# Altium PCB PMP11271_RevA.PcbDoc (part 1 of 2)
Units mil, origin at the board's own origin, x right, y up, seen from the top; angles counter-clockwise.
Board outline 3600 x 2200 mil, 4 copper layers (Top Layer, Signal Layer 1, Signal Layer 2, Bottom Layer), stack 61.2 mil thick; 97 components, 68 nets, 279 pads, 71 vias.
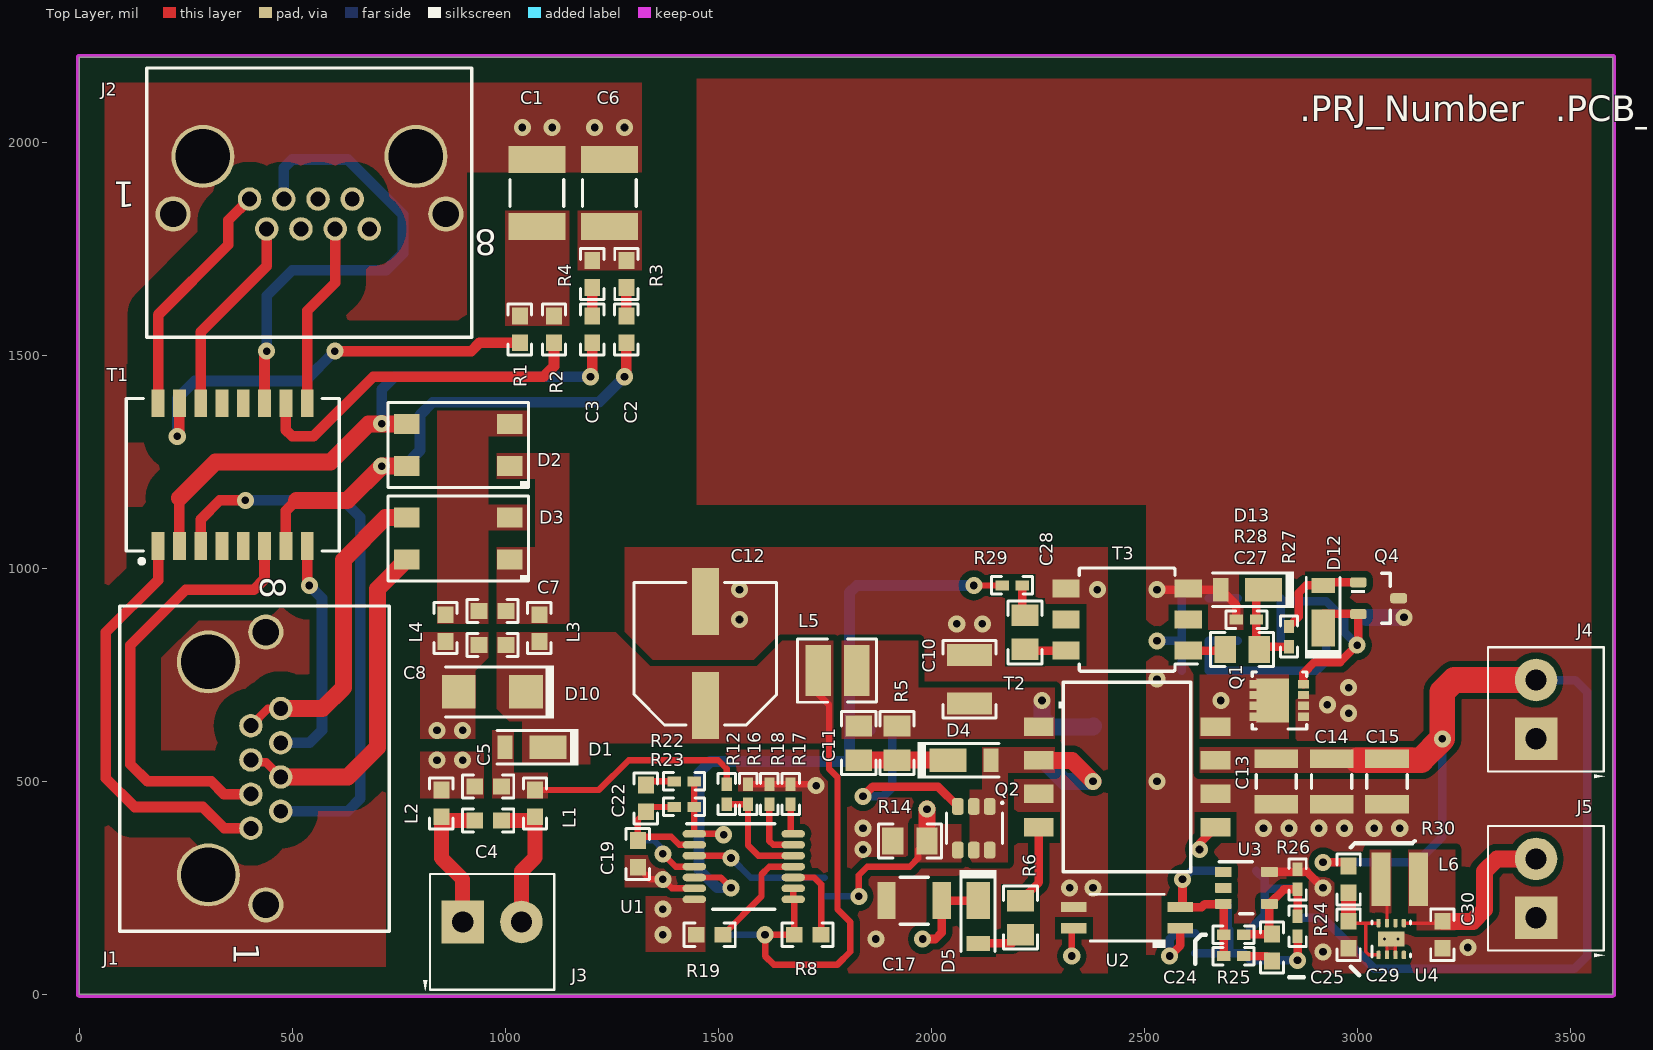
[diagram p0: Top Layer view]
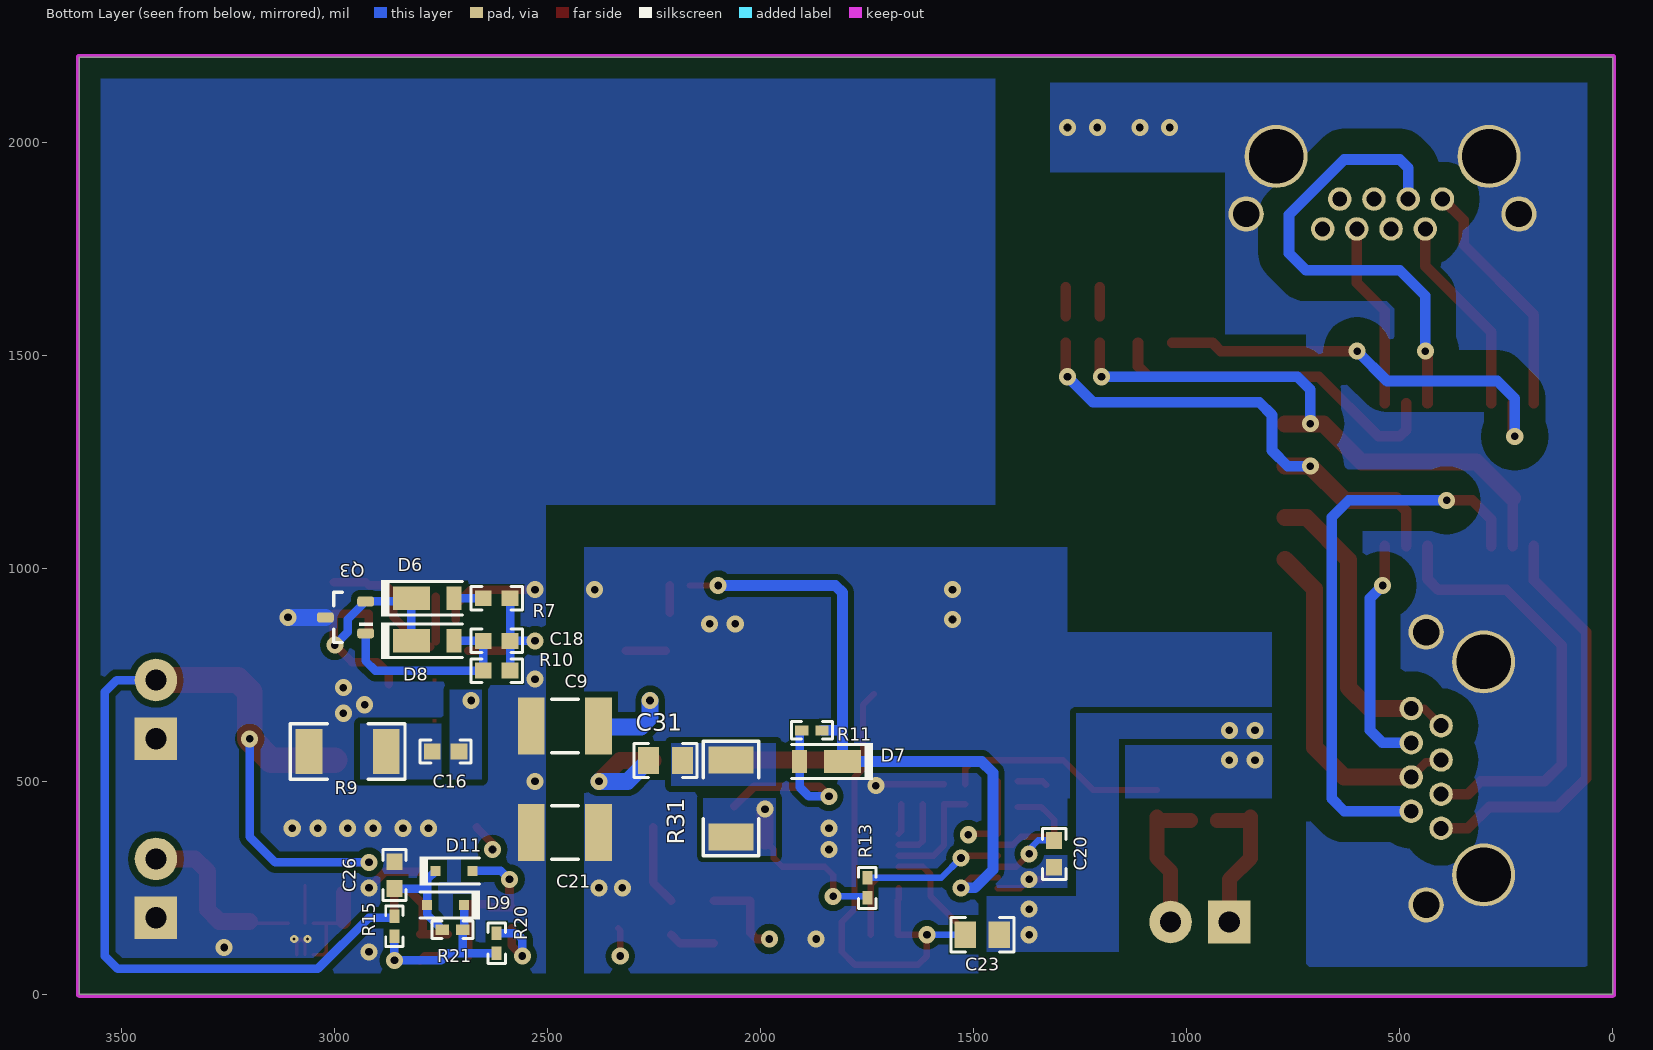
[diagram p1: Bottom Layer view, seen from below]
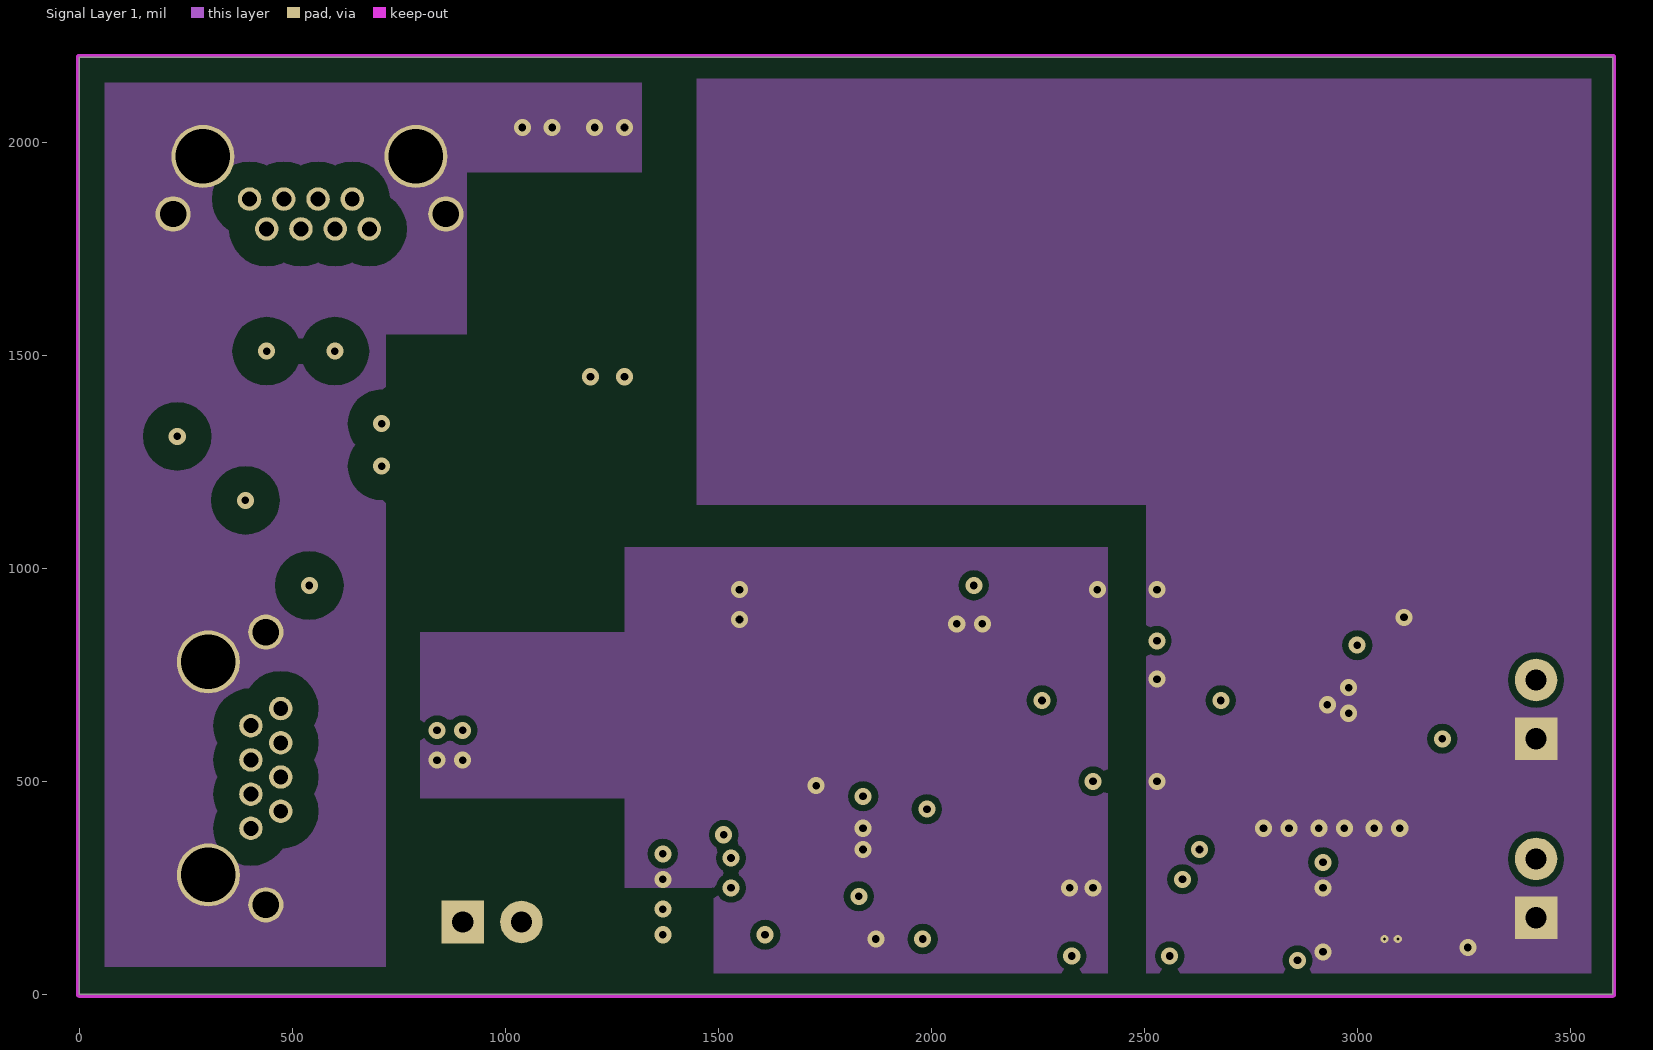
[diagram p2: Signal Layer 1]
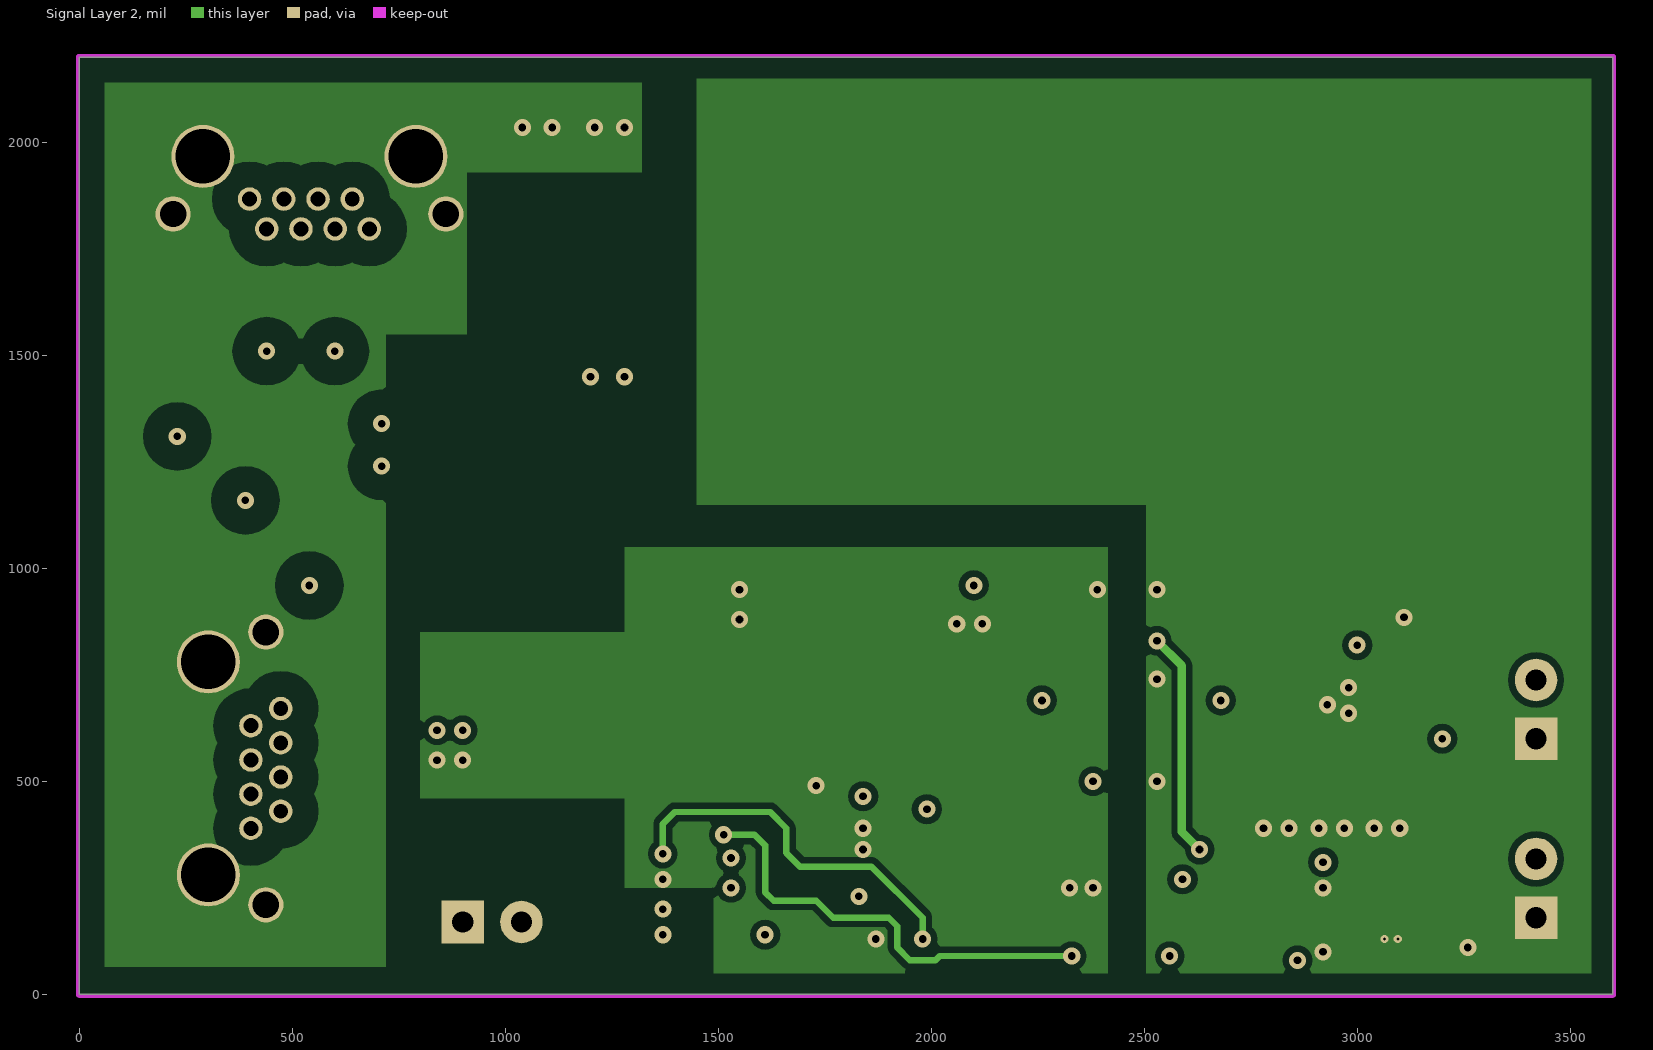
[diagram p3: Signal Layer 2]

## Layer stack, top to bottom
Top Solder: solder mask 0.4, Solder Resist, Dk 3.5
Top Layer: signal copper 2.8
Dielectric1: core 15, FR-4, Dk 4.8
Signal Layer 1: signal copper 2.8
Dielectric 3: prepreg 20, Dk 4.2
Signal Layer 2: signal copper 2.8
Dielectric 2: core 15, Dk 4.2
Bottom Layer: signal copper 2.8
Bottom Solder: solder mask 0.4, Solder Resist, Dk 3.5

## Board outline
0,0 3600,0 3600,2200 0,2200

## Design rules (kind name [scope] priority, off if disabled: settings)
AcuteAngle [All] p1: minimum=4.50000000000000E+0001 checktracksonly=FALSE
AssemblyTestPointUsage [All] p1: valid=2
Clearance Clearance_4 [InNamedPolygon('Signal Layer 2-EARTH')] p1: gap=60
Clearance Clearance_3 [InNamedPolygon('Signal Layer 1-EARTH')] p2: gap=60
Clearance Clearance_2 [InNamedPolygon('Top Layer-EARTH')] p3: gap=60
Clearance Clearance_1 [InNamedPolygon('Bottom Layer-EARTH')] p4: gap=60
Clearance Clearance_Keepouts [((IsTrack Or IsArc) And Not InPoly) And IsFree and IsKeepOut vs ((IsTrack Or IsArc) And Not InPoly) And IsFree and IsKeepOut] p5: gap=0
Clearance Clearance_BoardEdge_MountingHoles [OnCopper and InComponentClass('Mounting Holes') vs IsKeepOut] p6: gap=40
Clearance Clearance_BoardEdge_Poly [OnCopper and InPoly vs IsKeepOut] p7: gap=25
Clearance Clearance_BoardEdge [OnCopper and Not InComponentClass('Logo') and not InComponentClass('FiducialMark') and not InRegion(1000,500,4000,800) and Not IsKeepout vs IsKeepOut] p8: gap=50
Clearance Clearance_Poly [InPolygon] p9: gap=15
Clearance [All] p10: gap=7.87
ComponentClearance ComponentClearance_MountingHoles_FiducialMarks [InComponentClass('Mounting Holes') vs InComponentClass('FiducialMark')] p1: gap=50 collisioncheckmode=3 verticalgap=10 showdistances=FALSE
ComponentClearance ComponentClearance_Shunt [InComponentClass('Header') vs InComponentClass('Shunt')] p2: gap=0 collisioncheckmode=3 verticalgap=0 showdistances=FALSE
ComponentClearance ComponentClearance_Logo [InComponentClass('Logo')] p3: gap=50 collisioncheckmode=3 verticalgap=10 showdistances=FALSE
ComponentClearance ComponentClearance_ScrewToNut [(HasFootprint('NY PMS 440 0025 PH')) vs (HasFootprint('Keystone_1902C'))] p4: gap=5 collisioncheckmode=3 verticalgap=10 showdistances=FALSE
ComponentClearance ComponentClearance_MountingHoles [InComponentClass('Mounting Holes')] p5: gap=250 collisioncheckmode=3 verticalgap=100000 showdistances=FALSE
ComponentClearance ComponentClearance_SmallPassives [HasFootprint('0201*') or HasFootprint('0402*') or HasFootprint('0508') or HasFootprint('0603*') or HasFootprint('0612') or HasFootprint('0805*') or HasFootprint('0815*') or HasFootprint('0830*') or HasFootprint('1206*') or HasFootprint('1210*') or HasFootprint('1808*') or HasFootprint('1812*') or HasFootprint('1825*') or HasFootprint('2010*') or HasFootprint('2220*') or HasFootprint('2225*') or HasFootprint('2512*') or HasFootprint('2728*') or HasFootprint('3518*') vs HasFootprint('0201*') or HasFootprint('0402*') or HasFootprint('0508') or HasFootprint('0603*') or HasFootprint('0612') or HasFootprint('0805*') or HasFootprint('0815*') or HasFootprint('0830*') or HasFootprint('1206*') or HasFootprint('1210*') or HasFootprint('1808*') or HasFootprint('1812*') or HasFootprint('1825*') or HasFootprint('2010*') or HasFootprint('2220*') or HasFootprint('2225*') or HasFootprint('2512*') or HasFootprint('2728*') or HasFootprint('3518*')] p6: gap=20 collisioncheckmode=3 verticalgap=10 showdistances=FALSE
ComponentClearance ComponentClearance_THtoSMT [IsThruComponent vs IsSMTComponent] p7: gap=50 collisioncheckmode=3 verticalgap=30 showdistances=FALSE
ComponentClearance ComponentClearance_THtoTH [IsThruComponent vs IsThruComponent] p8: gap=50 collisioncheckmode=3 verticalgap=30 showdistances=FALSE
ComponentClearance [All] p9: gap=20 collisioncheckmode=3 verticalgap=10 showdistances=FALSE
DiffPairsRouting [All] p1: maxlimit=100 minlimit=10 mostfreqgap=10 toplayer_minwidth=15 toplayer_maxwidth=15 toplayer_prefwidth=15 midlayer1_minwidth=15 midlayer1_maxwidth=15 midlayer1_prefwidth=15 midlayer2_minwidth=15 midlayer2_maxwidth=15 midlayer2_prefwidth=15 bottomlayer_minwidth=15 bottomlayer_maxwidth=15 bottomlayer_prefwidth=15 maxuncoupledlength=1000
FabricationTestPointUsage TestPointUsage [All] p1: valid=2 allowmultiple=FALSE
FabricationTestpoint Testpoint [All] p1: side=3 testpointundercomponent=TRUE minsize=40 maxsize=100 preferedsize=60 minholesize=0 maxholesize=40 preferedholesize=32 testpointgrid=1 allowsidetop=TRUE allowsidebottom=TRUE usegrid=TRUE gridtolerance=0.01
FanoutControl Fanout_LCC [IsLCC] p1: bgadir=Out bgaviamode=Centered fanoutstyle=Auto fanoutdirection=Alternating viagrid=1 // Fanout_LCC (Default Rule)
FanoutControl Fanout_BGA [IsBGA] p2: bgadir=Out bgaviamode=Centered fanoutstyle=Auto fanoutdirection=Alternating viagrid=1 // Fanout_BGA (Default Rule)
FanoutControl Fanout_Default [All] p4: bgadir=Out bgaviamode=Centered fanoutstyle=Auto fanoutdirection=Alternating viagrid=1 // Fanout_Default (Default Rule)
FanoutControl Fanout_Small [(CompPinCount < 5)] p5: bgadir=Out bgaviamode=Centered fanoutstyle=Auto fanoutdirection=OutThenIn viagrid=1 // Fanout_Small (Default Rule)
HoleSize [All] p1: absolutevalues=TRUE maxlimit=251 minlimit=8 maxpercent=80.000 minpercent=20.000
MinimumAnnularRing MinimumAnnularRing_ThermalPadVias [IsVia and InAnyComponent] p1: minimumring=5.91
MinimumAnnularRing [All] p2: minimumring=9
MinimumSolderMaskSliver MinimumSolderMaskSliver_Logo [InComponentClass('Logo') vs InComponentClass('Logo')] p1: minsoldermaskwidth=0.7
MinimumSolderMaskSliver [All] p2: minsoldermaskwidth=3.94
PlaneConnect [All] p1: planeconnectstyle=Relief reliefexpansion=10 reliefentries=4 reliefconductorwidth=10 reliefairgap=10
PolygonConnect [All] p1: connectstyle=Direct reliefconductorwidth=10 reliefentries=4 polygonreliefangle="90 Angle" airgapwidth=10
RoutingVias ThermalPadVias [IsVia and InAnyComponent] p1: holewidth=7.87 width=19.68 viastyle="Through Hole" minholewidth=7.87 minwidth=19.68 maxholewidth=12.99 maxwidth=23.62
RoutingVias [All] p2: holewidth=18 width=40 viastyle="Through Hole" minholewidth=7.87 minwidth=26 maxholewidth=40 maxwidth=65
SilkToBoardRegionClearance [Not ((IsComment or IsDesignator) And (Hide <> 'False')) and not InRegion(1000,500,4000,800)] p1:
SilkToSilkClearance SilkToSilkClearance_Pb-FreeLogo [(HasFootprint('Pb-Free_Overlay_Medium') OR HasFootprint('Pb-Free_Overlay_Small')) vs (HasFootprint('Pb-Free_Overlay_Medium') OR HasFootprint('Pb-Free_Overlay_Small'))] p1: silktosilkclearance=0
SilkToSilkClearance [All] p2: silktosilkclearance=2
SilkToSolderMaskClearance "Silk to Solder Mask Opening" [All] p1: minsilkscreentomaskgap=2 clearancetoexposedcopper=FALSE
SolderMaskExpansion [All] p1: expansion=1.97
UnpouredPolygon [All] p1: allowunpoured=FALSE
Width [All] p1: maxlimit=100 minlimit=6 preferedwidth=10 checkconnectedcopper=TRUE
14 further rules are at their usual default settings.

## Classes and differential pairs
component class PMP11271_RevB_SH1: C1 C2 C3 C4 C5 C6 C7 C8 D1 D2 D3 J1 J2 J3 L1 L2 L3 L4 R1 R2 R3 R4 T1
component class PMP11271_RevB_SH2: C9 C10 C11 C12 C13 C14 C15 C16 C17 C18 C19 C20 C21 C22 C23 C24 C25 C26 C27 C28 C29 C30 C31 D4 D5 D6 D7 D8 D9 D10 D11 D12 D13 J4 J5 L5 L6 Q1 Q2 Q3 Q4 R5 R6 R7 R8 R9 R10 R11 R12 R13 R14 R15 R16 R17 R18 R19 R20 R21 R22 R23 R24 R25 R26 R27 R28 R29 R30 R31 T2 T3 U1 U2 U3 U4

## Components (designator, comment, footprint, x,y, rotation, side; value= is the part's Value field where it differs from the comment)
C1 "1812GC102KA1" 1812 1074.32,1881.17 r90 top
C2 "C1608X7R2A103K" 0603 1284.32,1561.17 r90 top
C3 "C1608X7R2A103K" 0603 1204.32,1561.17 r90 top
C4 "C1608X7R2A102K" 0603 960,408.35 r180 top
C5 "C1608X7R2A102K" 0603 960,488.35 r180 top
C6 "1812GC102KA1" 1812 1244.32,1881.17 r90 top
C7 "C1608X7R2A102K" 0603 970,900 r180 top
C8 "C1608X7R2A102K" 0603 970,820 r180 top
C9 "C4532X7R3D222K" 1812 2460,630 r180 bottom
C10 "GRM32ER72A225KA35L" 1210 2090,740 r90 top
C11 "C2012X7R2A104K" 0805_HV 1830,590 r270 top
C12 "EEE-FK1K100P" SM_RADIAL_E 1470,800 r90 top
C13 "C3225X5R0J107M" 1210L 2810,500 r270 top
C14 "C3225X5R0J107M" 1210L 2940,500 r270 top
C15 "C3225X5R0J107M" 1210L 3070,500 r270 top
C16 "GRM188R71H332KA01D" 0603 2740,570 r0 bottom
C17 "C3225X7R1C226K250AC" 1210_280 1960,220 r180 top
C18 "C1608C0G1H221J" 0603 2620,830 r180 bottom
C19 "C1608X7R1H104K" 0603 1311.32,330 r90 top
C20 "C1608X7R1C105K" 0603 1311.32,330 r270 bottom
C21 "C4532X7R3D222K" 1812 2460,380 r180 bottom
C22 "C1608X7R1H104K" 0603 1330,460 r90 top
C23 "C2012X7R2A104K" 0805_HV 1480,140 r180 bottom
C24 "GRM1535C1H101JDD5D" 0402 2710,140 r180 top
C25 "GRM188R71E123KA01D" 0603 2800,110 r270 top
C26 "C1608X7R1C105K" 0603 2860,280 r90 bottom
C27 "C2012X7R1E474K" 0805_HV 2730,810 r180 top
C28 "C2012X7R1E474K" 0805_HV 2220,850 r90 top
C29 "C1608X5R1A226M080AC" 0603_100 2980,140 r270 top
C30 "C1608X5R1A226M080AC" 0603_100 3200,140 r270 top
C31 "GRM21A5C2E680JW01D" 0805_HV 2223.78,549.37 r180 bottom
D1 "DFLS1100-7" powerDI123 1050,580 r180 top
D2 "HD01-T" MiniDIP 890,1290 r180 top
D3 "HD01-T" MiniDIP 890,1070 r180 top
D4 "DFLU1200-7" powerDI123 2090,550 r0 top
D5 "DFLU1200-7" powerDI123 2110,170 r270 top
D6 "DFLS1100-7" powerDI123 2770,930 r180 bottom
D7 "DFLU1200-7" powerDI123 1858.52,546.71 r0 bottom
D8 "DFLS1100-7" powerDI123 2770,830 r180 bottom
D9 "BAT54HT1G" sod-323 2740,210 r0 bottom
D10 "SMAJ58A" SMA 970,710 r180 top
D11 "BAT54HT1G" sod-323 2720,290 r180 bottom
D12 "DFLS1100-7" powerDI123 2920,910 r90 top
D13 "DFLS1100-7" powerDI123 2730,950 r180 top
J1 "1-406541-1" TEC_1-406541-1 410,530 r270 top
J2 "1-406541-1" TEC_1-406541-1 540,1860 r180 top
J3 "ED555/2DS" TERM_BLK_ED555-2DS 900,170 r0 top
J4 "ED555/2DS" TERM_BLK_ED555-2DS 3420,600 r90 top
J5 "ED555/2DS" TERM_BLK_ED555-2DS 3420,180 r90 top
L1 "MPZ1608S221A" 0603 1070,448.35 r90 top
L2 "MPZ1608S221A" 0603 850,448.35 r90 top
L3 "MPZ1608S221A" 0603 1080,860 r270 top
L4 "MPZ1608S221A" 0603 860,860 r270 top
L5 "ME3220-103KLB" ME3220 1780,760 r0 top
L6 "XFL3012-152MEB" XFL3012 3100,270 r0 top
Q1 "CSD17579Q3A" TRANS_NexFET_Q3A 2810,690 r180 top
Q2 "FDC86244" SOT-6 2100,390 r270 top
Q3 "MMBT3906" SOT-23 2975,885 r0 bottom
Q4 "MMBT3906" SOT-23 3050,930 r0 top
R1 "CRCW060375R0FKEA" 0603 1034.32,1561.17 r90 top
R2 "CRCW060375R0FKEA" 0603 1114.32,1561.17 r90 top
R3 "CRCW060375R0FKEA" 0603 1284.32,1691.17 r270 top
R4 "CRCW060375R0FKEA" 0603 1204.32,1691.17 r270 top
R5 "CRCW080539K0JNEA" 0805_HV 1920,590 r90 top
R6 "CRCW080520R0JNEA" 0805_HV 2210,180 r90 top
R7 "CRCW060310R0JNEA" 0603 2620,930 r0 bottom
R8 "CRCW060324K9FKEA" 0603 1710,140 r180 top
R9 "CRCW20102R20JNEF" 2010 2970,570 r180 bottom
R10 "CRCW06034K99FKEA" 0603 2620,760 r0 bottom
R11 "CRCW0402100RFKED" 0402 1880,620 r0 bottom
R12 "CRCW0402374KFKED" 0402 1520,470 r90 top
R13 "CRCW04021K00FKED" 0402 1750,250 r90 bottom
R14 "ERJ-6RQFR47V" 0805_HV 1950,360 r0 top
R15 "ERJ-2GE0R00X" 0402 2860,160 r90 bottom
R16 "CRCW040220K0FKED" 0402 1570,470 r270 top
R17 "CRCW040237K4FKED" 0402 1670,470 r270 top
R18 "CRCW0402100KFKED" 0402 1620,470 r270 top
R19 "CRCW060390R9FKEA" 0603 1480,140 r0 top
R20 "CRCW0402649RFKED" 0402 2620,120 r270 bottom
R21 "CRCW040210K0FKED" 0402 2723.76,151.79 r180 bottom
R22 "CRCW0402499RFKED" 0402 1420,500 r180 top
R23 "CRCW04022K00FKED" 0402 1420,440 r180 top
R24 "CRCW040210K0FKED" 0402 2860,160 r270 top
R25 "CRCW040210K0FKED" 0402 2710,90 r180 top
R26 "CRCW04023K24FKED" 0402 2860,270 r270 top
R27 "CRCW040210R0JNED" 0402 2840,840 r270 top
R28 "CRCW040210K0FKED" 0402 2740,880 r0 top
R29 "ERJ-2GE0R00X" 0402 2190,960 r180 top
R30 "ERJ-3GEY0R00V" 0603 2980,270 r270 top
R31 "CRCW201075R0JNEF" 2010 2070,460 r90 bottom
T1 "H2019FNLT" PULSE_H2019FNL 360,1220 r90 top
T2 "LDT0807-50" Linkcom_LDT0807-50 2460,510 r0 top
T3 "760301107" Wurth_WE-GDT_EP5 2460,880 r180 top
U1 "TPS23753APW" PW0014A_N 1560,300 r0 top
U2 "HMHA2801A" MFP04A 2460,180 r180 top
U3 "TLV431AIDBV" DBV0005A_N 2740,250 r0 top
U4 "TPS62082DSGR" DSG0008A 3080,130 r90 top

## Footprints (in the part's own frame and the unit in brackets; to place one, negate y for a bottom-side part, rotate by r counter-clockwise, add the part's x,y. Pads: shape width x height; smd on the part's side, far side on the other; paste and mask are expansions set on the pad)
0402 [mm] "0402 from SM-752 data"
  rect 0.8x0.6 smd: 1(-0.6,0) 2(0.6,0)
  silkscreen extent -1.22,-0.52 1.22,0.52, body extent -0.55,-0.3 0.55,0.3, height 0.6
0603 [mm] "0603 from SM-752 data"
  rect 1x0.95 smd: 1(-0.8,0) 2(0.8,0)
  silkscreen extent -1.52,-0.69 1.52,0.69, body extent -0.87,-0.47 0.87,0.47, height 0.85
0603_100 [mm] "SMD, 2-Leads, Body 1.6x0.8mm"
  rect 1x0.95 smd: 1(-0.8,0) 2(0.8,0)
  silkscreen extent -1.52,-0.69 1.52,0.69, body extent -0.87,-0.47 0.87,0.47, height 1
0805_HV [mil] "0805 with 30mil clearance between pads"
  rect 50x63 smd: 1(-40,0) 2(40,0)
  silkscreen extent -74,-40 74,40, body extent -43,-29 43,29, height 57
1210 [mm] "1210 from SM-752 data"
  rect 1.3x2.7 smd: 1(-1.45,0) 2(1.45,0)
  silkscreen extent -2.32,-1.57 2.32,1.57, body extent -1.7,-1.35 1.7,1.35, height 1.35
1210_280 [mm] "SMD, 2-Leads, Body 3.6x2.8mm, Height 2.8mm"
  rect 1.1x2.2 smd: 1(-1.65,0) 2(1.65,0)
  silkscreen extent -0.84,-1.4 0.84,1.4, body extent -1.8,-1.4 1.8,1.4, height 2.8
1210L [mm] "1210 from SM-752 data"
  rect 1.1x2.6 smd: 1(-1.35,0) 2(1.35,0)
  silkscreen extent -0.4,-1.2 0.4,1.2, body extent -1.7,-1.35 1.7,1.35, height 1.35
1812 [mm]
  rect 1.6x3.4 smd: 1(-2,0) 2(2,0)
  silkscreen extent -0.8,-1.6 0.8,1.6, body extent -2.4,-1.7 2.4,1.7, height 1.35
2010 [mm] "Chip Capacitor, Body 5.08x2.54mm, IPC Medium Density"
  rect 1.6x2.7 smd: 1(-2.3,0) 2(2.3,0)
  silkscreen extent -3.42,-1.65 3.42,1.65, body extent -2.73,-1.45 2.73,1.45, height 1.66
DBV0005A_N [mm] "SOT23, 5-Leads, Body 2.9x1.6mm, Pitch 0.95mm, Lead Span 2.8mm, IPC Medium Density"
  rrect17% 1x0.6 smd: 1(-1.375,0.95) 2(-1.375,0) 3(-1.375,-0.95) 4(1.375,-0.95) 5(1.375,0.95)
  silkscreen extent -1.63,-1.55 0.38,1.55, body extent -1.42,-1.46 1.42,1.46, height 1.09
DSG0008A [mm] "SON, 8-Leads, Body 2x2mm, Pitch 0.5mm, Thermal Pad 1.6x0.9mm, TI Recommended"
  rrect40% 0.5x0.25 smd: 1(-0.95,0.75) 2(-0.95,0.25) 3(-0.95,-0.25) 4(-0.95,-0.75) 5(0.95,-0.75) 6(0.95,-0.25) 7(0.95,0.25) 8(0.95,0.75)
  rrect11% 0.9x1.6 smd paste-0.45: 9(0,0)
  silkscreen extent -1.07,-1.15 1.07,1.15, body extent -1.05,-1.05 1.05,1.05, height 0.8
Linkcom_LDT0807-50 [mm] "SMD, 8-Leads, Body 11.3x7.6mm, Pitch 2mm"
  rect 1.77x1.1 smd: 1(-5.265,3) 2(-5.265,1) 3(-5.265,-1) 4(-5.265,-3) 5(5.265,-3) 6(5.265,-1) 7(5.265,1) 8(5.265,3)
  silkscreen extent -4.1,-5.65 3.8,5.65, body extent -6,-5.65 6,5.65, height 5.71
ME3220 [mm] "Coilcraft SMT Power Inductor ME3220 inductors"
  rect 1.52x3.05 smd: 1(-1.145,0) 2(1.145,0)
  silkscreen extent -2.38,-1.88 2.34,1.88, body extent -1.75,-1.41 1.75,1.4
MFP04A [mm] "FAIRCHILD optocoupler"
  rect 1.52x0.61 smd: 1(-3.175,0.635) 2(-3.175,-0.635) 3(3.175,-0.635) 4(3.175,0.635)
  silkscreen extent -2.28,-1.4 2.2,1.8, body extent -3.6,-1.34 3.6,1.34, height 2.39
MiniDIP [mm] "Land pattern created based on STEP model."
  rect 1.52x1.2 smd: 1(-3.075,1.25) 2(-3.075,-1.25) 3(3.075,-1.25) 4(3.075,1.25)
  silkscreen extent -4.19,-2.54 4.19,2.54, body extent -3.5,-2.45 3.5,2.45, height 2.75
powerDI123 [mm] "Diodes Inc recommended land pattern, document number DS30628 Rev. 6-2"
  rect 2.2x1.4 smd: 1(-1.275,0)
  rect 0.9x1.4 smd: 2(1.275,0)
  silkscreen extent -3.1,-1.09 1.76,1.09, body extent -2.38,-0.97 1.52,0.96, height 1
PULSE_H2019FNL [mil] "PULSE"
  rect 65x30 smd paste+0: 1(-167.51,174.99) 2(-167.51,124.99) 3(-167.51,74.99) 4(-167.51,24.99) 5(-167.51,-25.01) 6(-167.51,-75.01) 7(-167.51,-125.01) 8(-167.51,-175.01) 9(167.49,-175.01) 10(167.49,-125.01) 11(167.49,-75.01) 12(167.49,-25.01) 13(167.49,24.99) 14(167.49,74.99) 15(167.49,124.99) 16(167.49,174.99)
  silkscreen extent -208,-250 179,250, body extent -179,-250 179,250, height 236
PW0014A_N [mm] "TSOP, 14-Leads, Body 5x4.4mm, Pitch 0.65mm, IPC Medium Density"
  oval 1.4x0.45 smd: 1(-2.95,1.95) 2(-2.95,1.3) 3(-2.95,0.65) 4(-2.95,0) 5(-2.95,-0.65) 6(-2.95,-1.3) 7(-2.95,-1.95) 8(2.95,-1.95) 9(2.95,-1.3) 10(2.95,-0.65) 11(2.95,0) 12(2.95,0.65) 13(2.95,1.3) 14(2.95,1.95)
  silkscreen extent -3.4,-2.55 1.85,2.55, body extent -3.21,-2.5 3.21,2.5, height 1
SM_RADIAL_E [mm] "8 x 6.2mm:  Panasonic E"
  rect 4x1.6 smd: 1(-3.1,0) 2(3.1,0)
  silkscreen extent -4.25,-4.25 4.25,4.25, body extent -4.26,-4.26 4.26,4.26, height 6.5
SMA [mm] "Molded Diode, 2-Leads, Body 4.3x2.6mm, IPC Medium Density, based on OnSemi component dimensions and land pattern"
  rect 2x2 smd: 1(-2,0) 2(2,0)
  silkscreen extent -3.66,-1.57 2.79,1.57, body extent -2.6,-1.3 2.6,1.3, height 2.42
sod-323 [mm] "NXP recommended land pattern"
  rect 0.6x0.6 smd paste-0.05: 1(-1.1,0) 2(1.1,0)
  silkscreen extent -2.06,-0.86 1.53,0.86, body extent -1.3,-0.67 1.3,0.68, height 1.1
SOT-6 [mm] "Fairchild recommended land pattern for SuperSOT-6 in MA06A.pdf dated 17OCT2005"
  rrect50% 1x0.7 smd: 1(-1.3,0.95) 2(-1.3,0) 3(-1.3,-0.95) 4(1.3,-0.95) 5(1.3,0) 6(1.3,0.95)
  silkscreen extent -1.52,-1.64 0.9,1.71, body extent -1.43,-1.48 1.43,1.49, height 0.9
SOT-23 [mm] "SOT23, 3-Leads, Body 2.9x1.3mm, Pitch 0.95mm, Lead Span 2.5mm, IPC Medium Density"
  rrect50% 1x0.6 smd: 1(-1.2,0.95) 2(-1.2,-0.95) 3(1.2,0)
  silkscreen extent -1.62,-1.5 0.7,1.5, body extent -1.16,-1.45 1.21,1.45, height 1
TEC_1-406541-1 [mm] "TE Connectivity"
  round 1.4 hole 0.89: 1(3.56,-0.18) 2(2.54,1.6) 3(1.52,-0.18) 4(0.5,1.6) 5(-0.52,-0.18) 6(-1.54,1.6) 7(-2.56,-0.18) 8(-3.58,1.6)
  round 2.1 hole 1.57: 9(8.12,0.71) 10(-8.14,0.71)
  round 3.759 hole 3.251: 11(6.34,-2.72) 12(-6.36,-2.72)
  silkscreen extent -9.69,-8 9.69,8.06, body extent -9.33,-8 9.31,7.75, height 14.8
TERM_BLK_ED555-2DS [mil]
  rect 100x100 hole 50: 1(0,0)
  round 100 hole 50: 2(138,0)
  silkscreen extent -93,-161 215,113, body extent -69,-150 207,106, height 323
TRANS_NexFET_Q3A [mm] "TI"
  rect 0.68x0.5 smd paste-1 mask+0.076: 1(-1.625,0.975) 2(-1.625,0.325) 3(-1.625,-0.325) 4(-1.625,-0.975)
  rect 0.41x0.5 smd paste-1 mask+0.076: 5(1.385,-0.975) 6(1.385,-0.325) 7(1.385,0.325) 8(1.385,0.975)
  rect 1.96x2.65 smd paste-3 mask+0.076: 9(0.205,0)
  Top Layer region: 1,1.1 1.24,1.1 1.24,1.325 1,1.325
  Top Layer region: 1,-1.325 1.24,-1.325 1.24,-1.1 1,-1.1
  silkscreen extent -1.82,-1.7 1.42,1.7, body extent -1.85,-1.65 1.45,1.66, height 0.91
Wurth_WE-GDT_EP5 [mm] "Gate Drive Transformer, EP5"
  rect 1.63x1.07 smd: 1(-3.645,1.85) 2(-3.645,0) 3(-3.645,-1.85) 4(3.645,-1.85) 5(3.645,0) 6(3.645,1.85)
  silkscreen extent -4.2,-3.08 2.85,3.08, body extent -3.85,-3.08 3.85,3.07, height 5.12
XFL3012 [mm] "Coilcraft"
  rect 1.12x3.2 smd: 1(-1.11,0) 2(1.11,0)
  body extent -1.6,-1.6 1.6,1.6, height 1.3

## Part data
C1 C6: "CAP, CERM, 1000pF, 2000V, +/-10%, X7R, 1812"
C2 C3: "CAP, CERM, 0.01uF, 100V, +/-10%, X7R, 0603"
C4 C5 C7 C8: "CAP, CERM, 1000pF, 100V, +/-10%, X7R, 0603"
C9 C21: "CAP, CERM, 2200pF, 2000V, +/-10%, X7R, 1812"
C10: "CAP, CERM, 2.2uF, 100V, +/-10%, X7R, 1210"
C11 C23: "CAP, CERM, 0.1uF, 100V, +/-10%, X7R, 0805"
C12: "CAP, AL, 10 µF, 80 V, +/- 20%, 2.4 ohm, SMD"
C13 C14 C15: "CAP, CERM, 100uF, 6.3V, +/-20%, X5R, 1210"
C16: "CAP, CERM, 3300 pF, 50 V, +/- 10%, X7R, 0603"
C17: "CAP, CERM, 22 µF, 16 V, +/- 10%, X7R, 1210"
C18: "CAP, CERM, 220 pF, 50 V, +/- 5%, C0G/NP0, 0603"
C19: "CAP, CERM, 0.1uF, 50V, +/-10%, X7R, 0603"
C20 C26: "CAP, CERM, 1uF, 16V, +/-10%, X7R, 0603"
C22: "CAP, CERM, 0.1 µF, 50 V, +/- 10%, X7R, 0603"
C24: "CAP, CERM, 100 pF, 50 V, +/- 5%, C0G/NP0, 0402"
C25: "CAP, CERM, 0.012 µF, 25 V, +/- 10%, X7R, 0603"
C27 C28: "CAP, CERM, 0.47 µF, 25 V, +/- 10%, X7R, 0805"
C29 C30: "CAP, CERM, 22 µF, 10 V, +/- 20%, X5R, 0603"
C31: "CAP, CERM, 68 pF, 250 V, +/- 5%, C0G/NP0, 0805"
D1 D6 D8 D12 D13: "Diode, Schottky, 100 V, 1 A, PowerDI123"
D2 D3: "Diode, Switching-Bridge, 100 V, 0.8 A, MiniDIP"
D4 D5 D7: "Diode, Superfast Rectifier, 200 V, 1 A, PowerDI123"
D9 D11: "Diode, Schottky, 30 V, 0.2 A, SOD-323"
D10: "Diode, TVS, Uni, 58V, 400W, SMA"
J1 J2: "RJ-45, Right Angle, No LED, tab up"
J3 J4 J5: "Terminal Block, 6A, 3.5mm Pitch, 2-Pos, TH"
L1 L2 L3 L4: "Ferrite Bead, 220 ohm @ 100 MHz, 2.2 A, 0603"
L5: "Inductor, Drum Core, Ferrite, 10 µH, 0.87 A, 0.43 ohm, SMD"
L6: "Inductor, Shielded, Composite, 1.5 µH, 2.2 A, 0.06 ohm, SMD"
Q1: "MOSFET, N-CH, 30 V, 20 A, SON 3.3x3.3mm"
Q2: "MOSFET, N-CH, 150 V, 2.3 A, SuperSOT-6"
Q3 Q4: library part "MMBT3906, Fairchild Semiconductor", "Transistor, PNP, 40V, 0.2A, SOT-23"
R1 R2 R3 R4: "RES, 75.0 ohm, 1%, 0.1W, 0603"
R5: "RES, 39k ohm, 5%, 0.125W, 0805"
R6: "RES, 20 ohm, 5%, 0.125W, 0805"
R7: "RES, 10 ohm, 5%, 0.1W, 0603"
R8: "RES, 24.9 k, 1%, 0.1 W, 0603"
R9: "RES, 2.2, 5%, 0.75 W, 2010"
R10: "RES, 4.99k ohm, 1%, 0.1W, 0603"
R11: "RES, 100, 1%, 0.063 W, 0402"
R12: "RES, 374 k, 1%, 0.063 W, 0402"
R13: "RES, 1.00 k, 1%, 0.063 W, 0402"
R14: "RES, 0.47, 1%, 0.125 W, 0805"
R15 R29: "RES, 0, 5%, 0.063 W, 0402"
R16: "RES, 20.0 k, 1%, 0.063 W, 0402"
R17: "RES, 37.4 k, 1%, 0.063 W, 0402"
R18: "RES, 100 k, 1%, 0.063 W, 0402"
R19: "RES, 90.9 ohm, 1%, 0.1W, 0603"
R20: "RES, 649, 1%, 0.063 W, 0402"
R21 R24 R25 R28: "RES, 10.0 k, 1%, 0.063 W, 0402"
R22: "RES, 499, 1%, 0.063 W, 0402"
R23: "RES, 2.00 k, 1%, 0.063 W, 0402"
R26: "RES, 3.24 k, 1%, 0.063 W, 0402"
R27: "RES, 10, 5%, 0.063 W, 0402"
R30: "RES, 0, 5%, 0.1 W, 0603"
R31: "RES, 75, 5%, 0.75 W, 2010"
T1: "Transformer, 350uH, SMT"
T2: "Transformer, 70 uH, SMT"
T3: "Transformer, Gate Drive, 650 uH, SMT"
U1: "IEEE 802.3-2005 PoE Interface and Isolated Converter Controller with Enhanced ESD Ride-Through, -40 to 125 degC, 14-pin SOP (PW14), Green (RoHS & no Sb/Br)"
U2: "Optocoupler, 3.75kV RMS, SMT"
U3: "LOW-VOLTAGE ADJUSTABLE PRECISION SHUNT REGULATOR, DBV0005A"
U4: "Buck Step Down Regulator with 2.3 to 6 V Input and 3.3 V Output, -40 to 85 degC, 8-Pin WSON (DSG), Green (RoHS & no Sb/Br)"

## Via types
v1: diameter 40, hole 18, Top Layer to Bottom Layer, 69 vias
v2: diameter 19.68, hole 7.87, Top Layer to Bottom Layer, 2 vias

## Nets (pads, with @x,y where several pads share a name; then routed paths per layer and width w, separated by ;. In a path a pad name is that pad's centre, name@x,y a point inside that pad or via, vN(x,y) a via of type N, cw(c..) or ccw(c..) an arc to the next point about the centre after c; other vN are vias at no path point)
5V: C13.1 C14.1 C15.1 J4.2 R15.2 R30.1 T2.7 | length 2643.9
  Top Layer w20: v1(2920,310) R30.1@2971.5,310
  Top Layer w60: 3000,550 3150,550 v1(3200,600) 3200,710 3228,738 J4.2@3420,738
  Bottom Layer w20: R15.2@2860,183.62 2863.62,180 2920,180 3040,60 3510,60 3540,90 3540,710 3512,738 J4.2@3420,738 ; v1(2920,310) 3140,310 3200,370 v1(3200,600)
AUX: C5.1 D1.2 L1.2 R12.2 | length 523.7
  Top Layer w15: L1.2@1070,479.84 1219.84,479.84 1290,550 1500,550 1520,530 R12.2@1520,493.62
EARTH: C1.2 C6.2 J1.9 J1.10 J1.11 J1.12 J2.9 J2.10 J2.11 J2.12
  other v1: 1040,2035 1110,2035 1210,2035 1280,2035
GATE: D7.1 R11.1 R29.2 U1.5 | length 1590.5
  Top Layer w15: U1.5@1443.86,274.41 1505.59,274.41 v1(1530,250) ; v1(2100,960) R29.2@2166.38,960
  Bottom Layer w25: v1(1530,250) 1497.34,250 1455,292.34 1455,520 1481.71,546.71 D7.1@1808.33,546.71 1808.33,620 ; R11.1@1856.38,620 1808.33,620 ; v1(2100,960) 1825,960 1808.33,943.33 1808.33,620
GD: D6.1 D8.1 D12.1 Q1.4 Q3.2 Q4.2 | length 700.5
  Top Layer w20: Q1.4@2873.98,728.39 2873.98,753.98 2900,780 2960,780 v1(3000,820) 3002.76,822.76 Q4.2@3002.76,892.6 ; D12.1@2920,859.8 2920,893.27 Q4.2@3002.09,893.27
  Bottom Layer w20: D8.1@2820.2,830 D6.1@2820.2,930 ; D6.1@2827.8,922.4 Q3.2@2927.76,922.4 2970,880.16 2970,850 v1(3000,820)
GND: C9.1 C13.2 C14.2 C15.2 C21.1 C26.2 C29.2 C30.2 D13.2 J4.1 J5.1 Q1.1 Q1.2 Q1.3 Q3.3 Q4.3 R9.1 R26.1 R28.1 T2.6 T3.3 U3.5 U4.2 U4.3 U4.9 | length 544.2
  Top Layer w8: U4.2@3070.16,92.6 U4.9@3070.16,120.16 ; U4.9@3072.13,122.13 U4.9@3080,130 3089.84,120.16 U4.3@3089.84,92.6
  Top Layer w20: v1(2530,950) D13.2@2679.8,950 2716.38,913.43 R28.1@2716.38,880 ; U3.5@2794.13,287.4 2882.6,287.4 v1(2920,250)
  Bottom Layer w40: Q3.3@3022.24,885 v1(3110,885)
  other v1: 2920,100 3260,110 2780,390 2840,390 2910,390 2970,390 3040,390 3100,390 2530,500 2980,660 2930,680 2980,720 2530,740
  other v2: 3064.25,130 3095.75,130
NetC1_1: C1.1 R1.2 R2.2
NetC2_1: C2.1 D2.4 T1.7 | length 1196.4
  Top Layer w25: T1.7@485.01,1052.49 485.01,1135.01 510,1160 ; v1(1280,1450) 1284.32,1454.32 C2.1@1284.32,1529.68
  Top Layer w40: 510,1160 630,1160 v1(710,1240) ; v1@710.79,1240.79 D2.4@768.94,1240.79
  Bottom Layer w25: v1(710,1240) 763.23,1240 800,1276.77 800,1360 830,1390 1220,1390 v1(1280,1450)
NetC2_2: C2.2 R3.2 | length 67
  Top Layer w25: C2.2@1284.32,1592.67 R3.2@1284.32,1659.68
NetC3_1: C3.1 D2.3 T1.2 | length 1382.5
  Top Layer w25: T1.2@235.01,1052.49 235.01,1165.01 ; v1(1200,1450) 1204.32,1454.32 C3.1@1204.32,1529.68
  Top Layer w40: 235.01,1165.01 320,1250 590,1250 679.21,1339.21 D2.3@768.94,1339.21
  Bottom Layer w25: v1(710,1340) 710,1420 740,1450 v1(1200,1450)
NetC3_2: C3.2 R4.2 | length 67
  Top Layer w25: C3.2@1204.32,1592.67 R4.2@1204.32,1659.68
NetC4_1: C4.1 J3.2 L1.1 | length 330.1
  Top Layer w35: C4.1@991.5,408.35 L1.1@1061.5,408.35 ; J3.2@1038,170 1038,289 1070,321 L1.1@1070,416.85
NetC4_2: C4.2 J3.1 L2.1 | length 337.6
  Top Layer w35: L2.1@850,416.85 850,320 900,270 J3.1@900,170 ; L2.1@858.5,408.35 C4.2@928.5,408.35
NetC6_1: C6.1 R3.1 R4.1
NetC7_1: C7.1 D2.1 D3.1 L3.1
NetC7_2: C7.2 D2.2 D3.2 L4.1
NetC9_2: C9.2 C10.1 C11.1 L5.2 R5.2 T2.1 | length 171.1
  Bottom Layer w40: v1(2260,690) 2260,650 2281.89,628.11 2379.37,628.11 C9.2@2381.26,630
NetC11_2: C11.2 D4.1 R5.1 | length 209.8
  Top Layer w40: C11.2@1830,550 R5.1@1920,550 D4.1@2039.8,550
NetC16_1: C16.1 Q1.5 Q1.6 Q1.7 Q1.8 Q1.9 T2.8
  other v1: 2680,690
NetC16_2: C16.2 R9.2
NetC17_1: C17.1 C20.1 D5.1 U1.4 | length 1253.3
  Top Layer w15: v1(1370,330) 1400,300 U1.4@1443.86,300
  Top Layer w20: v1(1980,130) 2010,130 2024.96,144.96 C17.1@2024.96,220 ; C17.1@2025.16,220.2 D5.1@2110,220.2
  Signal Layer 2 w15: v1(1370,330) 1370,400 1398.19,428.19 1621.81,428.19 1660,390 1660,332.06 1692.06,300.01 1859.99,300.01 1980,180 v1(1980,130)
  Bottom Layer w15: C20.1@1311.32,361.5 1348.5,361.5 1370,340 v1(1370,330)
NetC18_1: C18.1 D8.2 Q3.1 R10.2 | length 488.8
  Bottom Layer w20: D8.2@2719.8,830 C18.1@2651.5,830 R10.2@2651.5,760 2905,760 2927.76,782.76 Q3.1@2927.76,847.6
NetC18_2: C18.2 R7.1 R10.1 T2.5 | length 827.3
  Top Layer w20: v1(2630,340) 2630,354.61 T2.5@2667.28,391.89
  Signal Layer 2 w20: v1(2530,830) 2588.5,771.5 2588.5,381.5 v1(2630,340)
  Bottom Layer w20: v1(2530,830) C18.2@2588.5,830 ; R10.1@2588.5,760 C18.2@2588.5,830 ; R7.1@2588.5,930 C18.2@2588.5,830
NetC19_2: C19.2 C22.1 R23.2 U1.2 | length 289.7
  Top Layer w15: R23.2@1396.38,440 1341.5,440 C22.1@1330,428.5 1311.32,409.82 C19.2@1311.32,361.5 1319.82,370 1390,370 1408.82,351.18 U1.2@1443.86,351.18
NetC22_2: C22.2 R22.2 | length 69.9
  Top Layer w15: C22.2@1330,491.5 1338.5,500 R22.2@1396.38,500
NetC24_1: C24.1 C25.1 R24.1 R26.2 U3.4 | length 272.7
  Top Layer w20: C24.1@2735.12,141.5 C25.1@2800,141.5 ; C25.1@2794.13,147.36 U3.4@2794.13,212.6 2827.91,246.38 R26.2@2860,246.38 R24.1@2860,183.62
NetC24_2: C24.2 D11.2 R25.2 U2.2 U3.3 | length 388.4
  Top Layer w20: v1(2590,270) 2590,210 U2.2@2585,205 2635,205 2642.09,212.09 2686.38,212.09 C24.2@2686.38,140 R25.2@2686.38,90
  Bottom Layer w20: v1(2590,270) 2610,290 D11.2@2676.69,290
NetC25_2: C25.2 R25.1 | length 71.1
  Top Layer w20: R25.1@2733.62,90 2788.5,90 C25.2@2800,78.5
NetC26_1: C26.1 D9.2 D11.1 R21.1 | length 236.6
  Bottom Layer w20: R21.1@2747.38,151.79 2783.31,187.72 D9.2@2783.31,210 2783.31,270 D11.1@2763.31,290 ; 2784.8,248.5 C26.1@2860,248.5
NetC27_1: C27.1 D13.1 R27.2 R28.2 | length 167.9
  Top Layer w20: C27.1@2763.62,829.13 R28.2@2763.62,880 D13.1@2763.62,933.43 ; C27.1@2776.38,816.38 R27.2@2840,816.38
NetC27_2: C27.2 T3.1 | length 83.7
  Top Layer w20: T3.1@2603.5,807.17 C27.2@2687.17,807.17
NetC28_1: C28.1 T3.6 | length 93.7
  Top Layer w20: C28.1@2222.83,807.17 T3.6@2316.5,807.17
NetC28_2: C28.2 R29.1 | length 63.6
  Top Layer w20: C28.2@2213.62,896.38 R29.1@2213.62,960
NetC29_1: C29.1 R30.2 U4.1 U4.8 | length 234.3
  Top Layer w8: C29.1@2984.09,167.4 3020,167.4 ; U4.1@3050.47,92.6 3027.4,92.6 3020,100 3020,167.4 ; U4.8@3050.47,167.4 3020,167.4
  Top Layer w35: C29.1@2980,171.5 R30.2@2980,238.5
NetC30_1: C30.1 J5.2 L6.2 U4.5 | length 419.8
  Top Layer w8: U4.5@3109.53,167.4 C30.1@3195.91,167.4
  Top Layer w40: C30.1@3200,171.5 3271.5,171.5 3299,199 3299,289 3328,318 J5.2@3420,318
NetC31_1: C31.1 D4.2 Q2.1 Q2.2 Q2.5 Q2.6 T2.2 | length 284.4
  Top Layer w40: T2.2@2252.72,549.37 2330.63,549.37 v1(2380,500)
  Bottom Layer w40: C31.1@2263.78,549.37 2313.15,500 v1(2380,500)
NetC31_2: C31.2 R31.2
NetD3_3: D3.3 J1.7 J1.8 | length 744.1
  Top Layer w20: J1.7@402.91,630.79 443.07,670.94 J1.8@472.99,670.94
  Top Layer w40: J1.8@472.99,670.94 570.94,670.94 620,720 620,1020 719.21,1119.21 D3.3@768.94,1119.21
NetD3_4: D3.4 J1.4 J1.5 | length 811.9
  Top Layer w20: J1.5@402.91,550.47 408.49,544.9 438.41,544.9 J1.4@472.99,510.32
  Top Layer w40: J1.4@472.99,510.32 630.32,510.32 700,580 700,951.85 D3.4@768.94,1020.79
NetD5_2: D5.2 R6.1 | length 108.4
  Top Layer w20: D5.2@2110,119.8 2189.8,119.8 R6.1@2210,140
NetD6_2: D6.2 R7.2 | length 68.3
  Bottom Layer w20: R7.2@2651.5,930 D6.2@2719.8,930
